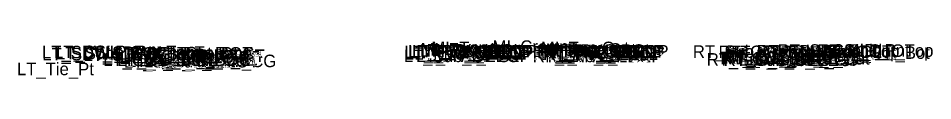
# Model space of a CAD drawing. Extents: x -26 to 4229, y -10 to 9523.
# Drawn here: x 67.4 to 214, y 4017.5 to 4023.7 of the extents above; entities that cross this region are included whole.
import ezdxf

# ---------------------------------------------------------------- set-up
doc = ezdxf.new("R2010")
doc.units = 0
doc.layers.add('Default', color=7, linetype='Continuous')

msp = doc.modelspace()

# ---------------------------------------------------------------- texts
at = {"layer": 'Default'}
for s, p in [('LT_PV1_OEEOP', (129.92, 4020.95)), ('LT_PV1_IEEOP', (130.57, 4020.95)), ('LT_PV1_PGL', (131.83, 4021.08)), ('MI_Face In', (131.95, 4021.25)), ('MI_Bot In', (132.93, 4021.08)), ('MI_Top In', (133.66, 4021.5)), ('MI_Crown', (143.47, 4021.69)), ('RT_PV1_OEEOP', (150.58, 4020.94)), ('MI_Face Out', (151.01, 4021.23)), ('MI_Top Out', (151.22, 4021.48)), ('RT_PV1_IEEOP', (151.22, 4020.94)), ('MI_Bot Out', (152.01, 4021.06)), ('RT_PV1_PGL', (152.48, 4021.06)), ('RT_Sub_Trench_Out_DLT', (175.59, 4020.89)), ('RT_SDWK_In_Top', (185.81, 4020.96)), ('RT_SDWK_Out_Top', (189.19, 4021.06)), ('RT_Shld_O', (195.54, 4021.05)), ('CSLP_Pnt', (197.87, 4021.09)), ('LT_SDWK_Out_Top', (71.24, 4020.82)), ('LT_SDWK_Out_Bot', (71.27, 4020.49)), ('LT_CSLP_Pnt', (73.17, 4020.85)), ('LT_Sub_Trench_Out_DLT', (73.49, 4020.65)), ('LT_SDWK_In_Top', (77.86, 4020.72)), ('LT_SDWK_In_Bot', (77.89, 4020.39)), ('LT_CG1_Shelf_Out', (81.05, 4019.59)), ('LT_CG_Top_Face', (82.76, 4020.61)), ('LT_CG_Top_BOC', (83.28, 4020.61)), ('LT_CG_Bot_BOC', (83.31, 4019.6)), ('LT_CG_Top_Gut', (83.74, 4020.11)), ('LT_Sub_OEOT_CG', (84.87, 4019.4)), ('LT_CG_Bot_IE', (87.41, 4019.65)), ('LT_PV2_OEOT', (87.67, 4019.98)), ('LT_PV3_OEOT', (87.67, 4019.73)), ('LT_PV1_OEOT', (88.24, 4020.23)), ('LT_Sub_OEEOP', (129.26, 4020.2)), ('LT_PV2_OEEOP', (129.35, 4020.83)), ('LT_PV3_OEEOP', (129.35, 4020.58)), ('LT_PV2_IEEOP', (130, 4020.83)), ('LT_PV2_PGL1', (130.93, 4020.83)), ('LT_PV3_PGL1', (130.93, 4020.58)), ('LT_PV2_PGL', (131.26, 4020.83)), ('LT_PV4_PGL', (131.26, 4020.2)), ('RT_Sub_OEEOP', (149.92, 4020.19)), ('RT_PV2_OEEOP', (150.01, 4020.81)), ('RT_PV3_OEEOP', (150.01, 4020.56)), ('RT_PV2_IEEOP', (150.66, 4020.81)), ('RT_PV2_PGL1', (151.58, 4020.81)), ('RT_PV3_PGL1', (151.58, 4020.56)), ('RT_PV2_PGL', (151.92, 4020.81)), ('RT_PV4_PGL', (151.92, 4020.19)), ('RT_Sub_OEOT_CG', (177.82, 4019.64)), ('RT_CG_Top_Face', (179.71, 4020.85)), ('RT_CG1_Shelf_Out', (180, 4019.83)), ('RT_CG_Bot_IE', (180.37, 4019.89)), ('RT_Sub_OEOT', (180.53, 4019.59)), ('RT_PV2_OEOT', (180.63, 4020.22)), ('RT_PV3_OEOT', (180.63, 4019.97)), ('RT_CG_Top_Gut', (180.69, 4020.35)), ('RT_PV1_OEOT', (181.19, 4020.47)), ('RT_CG_Top_BOC', (181.24, 4020.85)), ('RT_CG_Bot_BOC', (181.27, 4019.84)), ('RT_Sub_OEOP', (183.82, 4019.57)), ('RT_SDWK_In_Bot', (185.84, 4020.63)), ('RT_SDWK_Out_Bot', (189.22, 4020.73)), ('LT_Tie_Pt', (67.22, 4018.11)), ('LT_Sub_OEOP', (84.36, 4019.33)), ('LT_Sub_OEOT', (87.58, 4019.35))]:
    msp.add_text(s, height=2, dxfattribs=at).set_placement(p)

doc.saveas('drawing.dxf')
